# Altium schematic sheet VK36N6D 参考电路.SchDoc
size A4
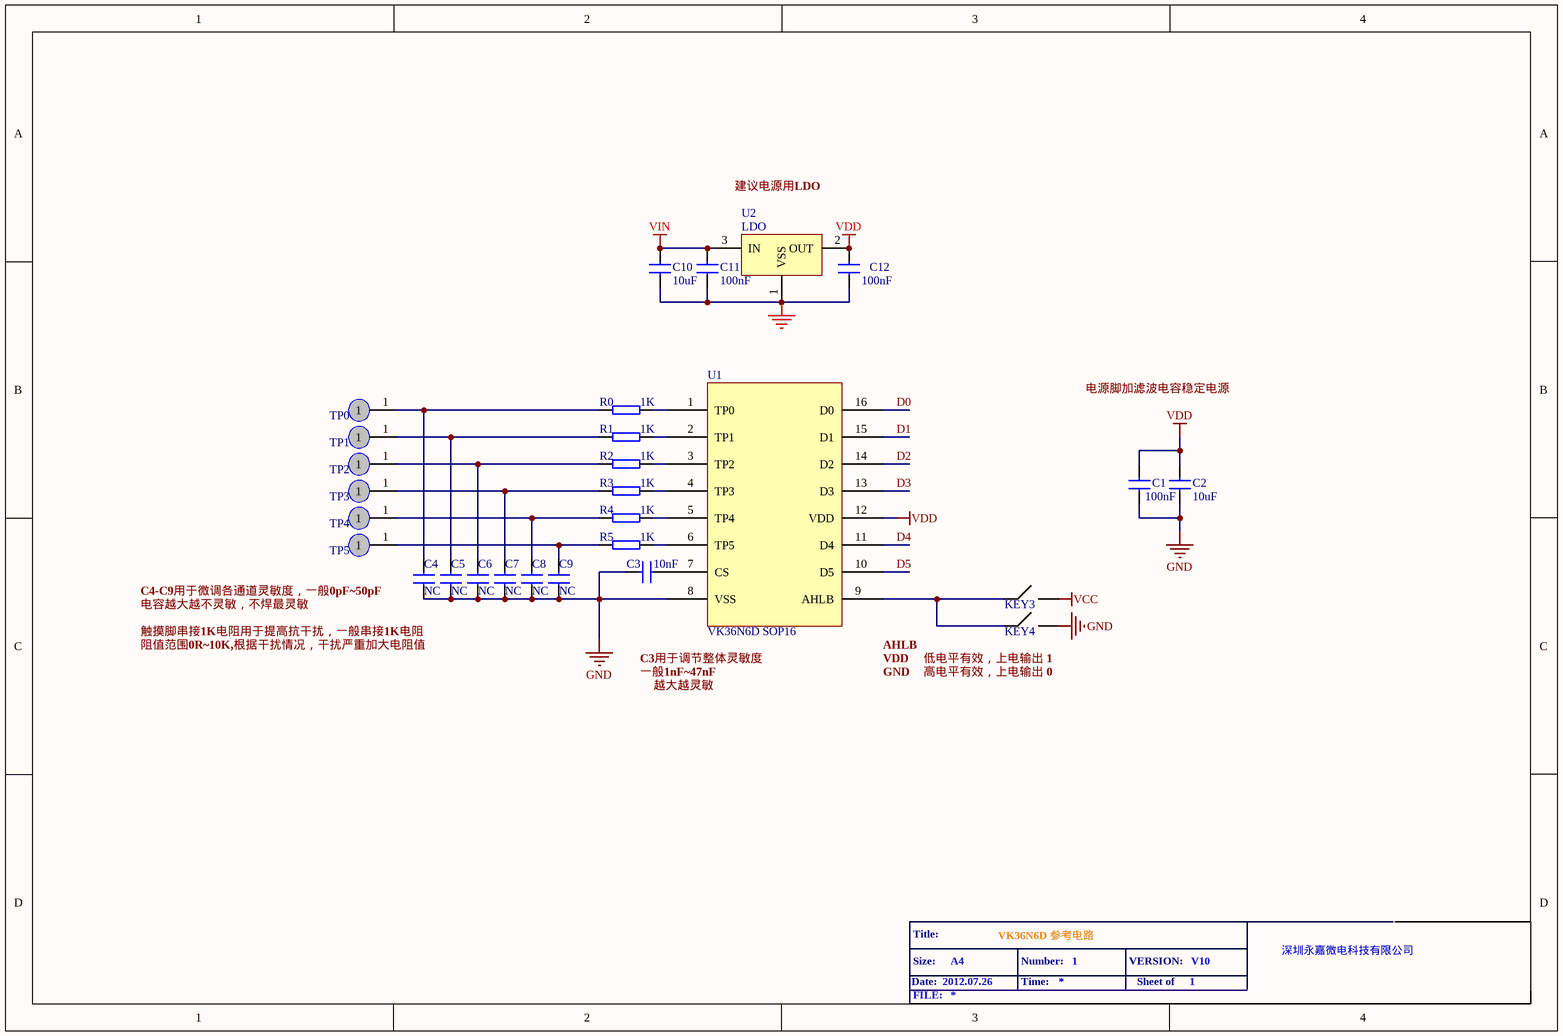
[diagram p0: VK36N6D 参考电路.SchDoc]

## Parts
C1  100nF  [0603-C]
C2  10uF  [0603-C]
C3  value 10nF  [0603-C]  (hidden comment: 10uF)
C4  value NC  [0603-C]  (hidden comment: 10uF)
C5  value NC  [0603-C]  (hidden comment: 10uF)
C6  value NC  [0603-C]  (hidden comment: 10uF)
C7  value NC  [0603-C]  (hidden comment: 10uF)
C8  value NC  [0603-C]  (hidden comment: 10uF)
C9  value NC  [0603-C]  (hidden comment: 10uF)
C10  10uF  [0805-C]
C11  100nF  [0805-C]
C12  100nF  [0805-C]
KEY3  单刀单掷开关  (value not drawn)
KEY4  单刀单掷开关  (value not drawn)
R0  1K  [0603-R]
R1  1K  [0603-R]
R2  1K  [0603-R]
R3  1K  [0603-R]
R4  1K  [0603-R]
R5  1K  [0603-R]
TP0  TPAD  [TP-PAD0]  (value not drawn)
TP1  TPAD  [TP-PAD0]  (value not drawn)
TP2  TPAD  [TP-PAD0]  (value not drawn)
TP3  TPAD  [TP-PAD0]  (value not drawn)
TP4  TPAD  [TP-PAD0]  (value not drawn)
TP5  TPAD  [TP-PAD0]  (value not drawn)
U1  VK36N6D SOP16
U2  LDO  [SOT-23]

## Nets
GND: C1.2 C2.2 C3.2 C4.1 C5.1 C6.1 C7.1 C8.1 C9.1 C10.2 C11.2 C12.2 U1.8(VSS) U2.1(VSS)
VDD: C1.1 C2.1 C12.1 U1.12(VDD) U2.2(OUT)
VIN: C10.1 C11.1 U2.3(IN)
D0: U1.16(D0)
D1: U1.15(D1)
D2: U1.14(D2)
D3: U1.13(D3)
D4: U1.11(D4)
D5: U1.10(D5)
NetC3_1: C3.1 U1.7(CS)
NetC4_2: C4.2 R0.1 TP0.1
NetC5_2: C5.2 R1.2 TP1.1
NetC6_2: C6.2 R2.2 TP2.1
NetC7_2: C7.2 R3.2 TP3.1
NetC8_2: C8.2 R4.2 TP4.1
NetC9_2: C9.2 R5.2 TP5.1
NetR0_2: R0.2 U1.1(TP0)
NetR1_1: R1.1 U1.2(TP1)
NetR2_1: R2.1 U1.3(TP2)
NetR3_1: R3.1 U1.4(TP3)
NetR4_1: R4.1 U1.5(TP4)
NetR5_1: R5.1 U1.6(TP5)

Not connected (* = marked no-connect by the designer): U1 9(AHLB)

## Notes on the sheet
- 建议电源用LDO
- 电源脚加滤波电容稳定电源
- 触摸脚串接1K电阻用于提高抗干扰，一般串接1K电阻
- 阻值范围0R
  0K,根据干扰情况，干扰严重加大电阻值
- C4-C9用于微调各通道灵敏度，一般0pF~50pF
- 电容越大越不灵敏，不焊最灵敏
- AHLB
- C3用于调节整体灵敏度
- 一般1nF~47nF
- 越大越灵敏
- VDD
- GND
- 低电平有效，上电输出 1
- 高电平有效，上电输出 0
- Date:
- Title:
- Size:
- 2012.07.26
- A4
- VK36N6D 参考电路
- Number:
- Time:
- 1
- VERSION:
- Sheet of
- V10
- 深圳永嘉微电科技有限公司
- FILE:
- Labels drawn without touching a wire or pin: GND, VCC

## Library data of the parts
C1-C12 = CAP: Capacitor
R0-R5 = RES: Resistor
TP0-TP5 = TPAD: TESTING
U2 = V6206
